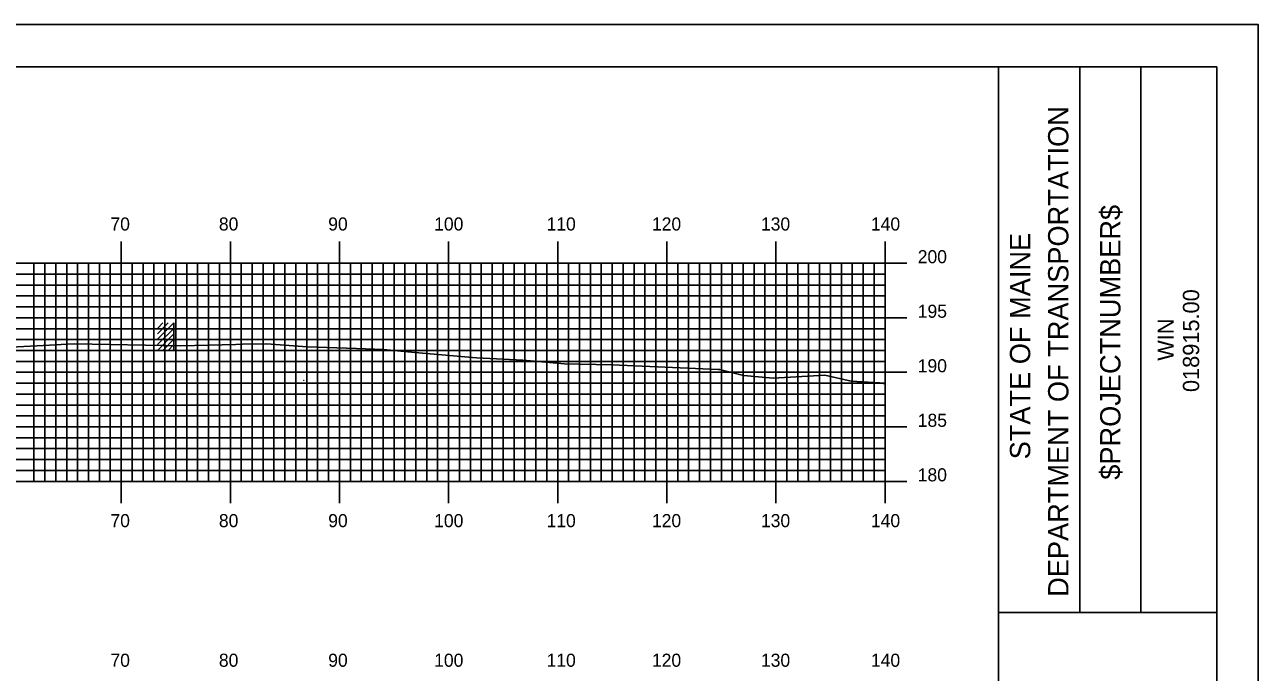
# Model space of a CAD drawing. Extents: x 1825147 to 1825490, y 442591 to 442811.
# Drawn here: x 1825373.5 to 1825486.6, y 442751.2 to 442810.5 of the extents above; entities that cross this region are included whole.
import ezdxf

# ---------------------------------------------------------------- set-up
doc = ezdxf.new("R2010")
doc.units = 0
for name, color, linetype in [('BORDER', 7, 'Continuous'), ('H_V ANNOTATION', 7, 'Continuous'), ('M_Buildings_Rooftop', 7, 'Continuous'), ('M_Utilities_Pole', 7, 'Continuous'), ('MAJOR', 7, 'Continuous'), ('MINOR', 7, 'Continuous'), ('PLOT BOUNDARY', 7, 'Continuous'), ('S_Roadway_Centerline', 7, 'Continuous')]:
    doc.layers.add(name, color=color, linetype=linetype)

msp = doc.modelspace()

# ---------------------------------------------------------------- linework, layer by layer
at = {"layer": 'BORDER'}
for p, q in [((1825462.76, 442596.67), (1825462.76, 442806.67)), ((1825470.22, 442756.66), (1825470.22, 442806.66)), ((1825475.81, 442756.66), (1825475.81, 442806.66)), ((1825462.76, 442756.65), (1825482.76, 442756.65))]:
    msp.add_line(p, q, dxfattribs=at)
msp.add_lwpolyline([(1825162.76, 442596.67), (1825482.76, 442596.67), (1825482.76, 442806.67), (1825162.76, 442806.67)], close=True, dxfattribs=at)
at = {"layer": 'M_Buildings_Rooftop'}
for p, q in [((1825385.68, 442781.7), (1825387.19, 442783.21)), ((1825385.68, 442782.19), (1825386.66, 442783.21)), ((1825385.68, 442782.68), (1825386.17, 442783.21)), ((1825385.68, 442781.21), (1825387.19, 442782.68)), ((1825387.19, 442780.68), (1825387.19, 442783.21)), ((1825385.68, 442780.68), (1825387.19, 442782.19)), ((1825386.17, 442780.68), (1825387.19, 442781.7)), ((1825386.66, 442780.68), (1825387.19, 442781.21))]:
    msp.add_line(p, q, dxfattribs=at)
at = {"layer": 'M_Utilities_Pole'}
msp.add_line((1825399.09, 442777.94), (1825399.09, 442777.93), dxfattribs=at)
msp.add_circle((1825399.09, 442777.93), 0.00417, dxfattribs=at)
at = {"layer": 'MAJOR'}
for p, q in [((1825382.36, 442790.67), (1825382.36, 442788.67)), ((1825392.36, 442790.67), (1825392.36, 442788.67)), ((1825402.36, 442790.67), (1825402.36, 442788.67)), ((1825412.36, 442790.67), (1825412.36, 442788.67)), ((1825422.36, 442790.67), (1825422.36, 442788.67)), ((1825432.36, 442790.67), (1825432.36, 442788.67)), ((1825442.36, 442790.67), (1825442.36, 442788.67)), ((1825452.36, 442790.67), (1825452.36, 442788.67)), ((1825172.36, 442788.67), (1825452.36, 442788.67)), ((1825172.36, 442788.67), (1825452.36, 442788.67)), ((1825382.36, 442768.67), (1825382.36, 442788.67)), ((1825392.36, 442768.67), (1825392.36, 442788.67)), ((1825402.36, 442768.67), (1825402.36, 442788.67)), ((1825412.36, 442768.67), (1825412.36, 442788.67)), ((1825422.36, 442768.67), (1825422.36, 442788.67)), ((1825432.36, 442768.67), (1825432.36, 442788.67)), ((1825442.36, 442768.67), (1825442.36, 442788.67)), ((1825454.37, 442788.67), (1825450.36, 442788.67)), ((1825452.36, 442768.67), (1825452.36, 442788.67)), ((1825452.36, 442768.67), (1825452.36, 442788.67)), ((1825172.36, 442783.67), (1825452.36, 442783.67)), ((1825454.37, 442783.67), (1825450.36, 442783.67)), ((1825172.36, 442778.67), (1825452.36, 442778.67)), ((1825454.37, 442778.67), (1825450.36, 442778.67)), ((1825172.36, 442773.67), (1825452.36, 442773.67)), ((1825454.37, 442773.67), (1825450.36, 442773.67)), ((1825172.36, 442768.67), (1825452.36, 442768.67)), ((1825172.36, 442768.67), (1825452.36, 442768.67)), ((1825382.36, 442766.66), (1825382.36, 442768.67)), ((1825392.36, 442766.66), (1825392.36, 442768.67)), ((1825402.36, 442766.66), (1825402.36, 442768.67)), ((1825412.36, 442766.66), (1825412.36, 442768.67)), ((1825422.36, 442766.66), (1825422.36, 442768.67)), ((1825432.36, 442766.66), (1825432.36, 442768.67)), ((1825442.36, 442766.66), (1825442.36, 442768.67)), ((1825454.37, 442768.67), (1825450.36, 442768.67)), ((1825452.36, 442766.66), (1825452.36, 442768.67))]:
    msp.add_line(p, q, dxfattribs=at)
at = {"layer": 'MINOR'}
for p, q in [((1825374.36, 442768.67), (1825374.36, 442788.67)), ((1825375.36, 442768.67), (1825375.36, 442788.67)), ((1825376.36, 442768.67), (1825376.36, 442788.67)), ((1825377.36, 442768.67), (1825377.36, 442788.67)), ((1825378.36, 442768.67), (1825378.36, 442788.67)), ((1825379.36, 442768.67), (1825379.36, 442788.67)), ((1825380.36, 442768.67), (1825380.36, 442788.67)), ((1825381.36, 442768.67), (1825381.36, 442788.67)), ((1825383.36, 442768.67), (1825383.36, 442788.67)), ((1825384.36, 442768.67), (1825384.36, 442788.67)), ((1825385.36, 442768.67), (1825385.36, 442788.67)), ((1825386.36, 442768.67), (1825386.36, 442788.67)), ((1825387.36, 442768.67), (1825387.36, 442788.67)), ((1825388.36, 442768.67), (1825388.36, 442788.67)), ((1825389.36, 442768.67), (1825389.36, 442788.67)), ((1825390.36, 442768.67), (1825390.36, 442788.67)), ((1825391.36, 442768.67), (1825391.36, 442788.67)), ((1825393.36, 442768.67), (1825393.36, 442788.67)), ((1825394.36, 442768.67), (1825394.36, 442788.67)), ((1825395.36, 442768.67), (1825395.36, 442788.67)), ((1825396.36, 442768.67), (1825396.36, 442788.67)), ((1825397.36, 442768.67), (1825397.36, 442788.67)), ((1825398.36, 442768.67), (1825398.36, 442788.67)), ((1825399.36, 442768.67), (1825399.36, 442788.67)), ((1825400.36, 442768.67), (1825400.36, 442788.67)), ((1825401.36, 442768.67), (1825401.36, 442788.67)), ((1825403.36, 442768.67), (1825403.36, 442788.67)), ((1825404.36, 442768.67), (1825404.36, 442788.67)), ((1825405.36, 442768.67), (1825405.36, 442788.67)), ((1825406.36, 442768.67), (1825406.36, 442788.67)), ((1825407.36, 442768.67), (1825407.36, 442788.67)), ((1825408.36, 442768.67), (1825408.36, 442788.67)), ((1825409.36, 442768.67), (1825409.36, 442788.67)), ((1825410.36, 442768.67), (1825410.36, 442788.67)), ((1825411.36, 442768.67), (1825411.36, 442788.67)), ((1825413.36, 442768.67), (1825413.36, 442788.67)), ((1825414.36, 442768.67), (1825414.36, 442788.67)), ((1825415.36, 442768.67), (1825415.36, 442788.67)), ((1825416.36, 442768.67), (1825416.36, 442788.67)), ((1825417.36, 442768.67), (1825417.36, 442788.67)), ((1825418.36, 442768.67), (1825418.36, 442788.67)), ((1825419.36, 442768.67), (1825419.36, 442788.67)), ((1825420.36, 442768.67), (1825420.36, 442788.67)), ((1825421.36, 442768.67), (1825421.36, 442788.67)), ((1825423.36, 442768.67), (1825423.36, 442788.67)), ((1825424.36, 442768.67), (1825424.36, 442788.67)), ((1825425.36, 442768.67), (1825425.36, 442788.67)), ((1825426.36, 442768.67), (1825426.36, 442788.67)), ((1825427.36, 442768.67), (1825427.36, 442788.67)), ((1825428.36, 442768.67), (1825428.36, 442788.67)), ((1825429.36, 442768.67), (1825429.36, 442788.67)), ((1825430.36, 442768.67), (1825430.36, 442788.67)), ((1825431.36, 442768.67), (1825431.36, 442788.67)), ((1825433.36, 442768.67), (1825433.36, 442788.67)), ((1825434.36, 442768.67), (1825434.36, 442788.67)), ((1825435.36, 442768.67), (1825435.36, 442788.67)), ((1825436.36, 442768.67), (1825436.36, 442788.67)), ((1825437.36, 442768.67), (1825437.36, 442788.67)), ((1825438.36, 442768.67), (1825438.36, 442788.67)), ((1825439.36, 442768.67), (1825439.36, 442788.67)), ((1825440.36, 442768.67), (1825440.36, 442788.67)), ((1825441.36, 442768.67), (1825441.36, 442788.67)), ((1825443.36, 442768.67), (1825443.36, 442788.67)), ((1825444.36, 442768.67), (1825444.36, 442788.67)), ((1825445.36, 442768.67), (1825445.36, 442788.67)), ((1825446.36, 442768.67), (1825446.36, 442788.67)), ((1825447.36, 442768.67), (1825447.36, 442788.67)), ((1825448.36, 442768.67), (1825448.36, 442788.67)), ((1825449.36, 442768.67), (1825449.36, 442788.67)), ((1825450.36, 442768.67), (1825450.36, 442788.67)), ((1825451.36, 442768.67), (1825451.36, 442788.67)), ((1825172.36, 442787.67), (1825452.36, 442787.67)), ((1825452.36, 442787.67), (1825450.36, 442787.67)), ((1825172.36, 442786.67), (1825452.36, 442786.67)), ((1825452.36, 442786.67), (1825450.36, 442786.67)), ((1825172.36, 442785.67), (1825452.36, 442785.67)), ((1825452.36, 442785.67), (1825450.36, 442785.67)), ((1825172.36, 442784.67), (1825452.36, 442784.67)), ((1825452.36, 442784.67), (1825450.36, 442784.67)), ((1825172.36, 442782.67), (1825452.36, 442782.67)), ((1825452.36, 442782.67), (1825450.36, 442782.67)), ((1825172.36, 442781.67), (1825452.36, 442781.67)), ((1825452.36, 442781.67), (1825450.36, 442781.67)), ((1825172.36, 442780.67), (1825452.36, 442780.67)), ((1825452.36, 442780.67), (1825450.36, 442780.67)), ((1825172.36, 442779.67), (1825452.36, 442779.67)), ((1825452.36, 442779.67), (1825450.36, 442779.67)), ((1825172.36, 442777.67), (1825452.36, 442777.67)), ((1825452.36, 442777.67), (1825450.36, 442777.67)), ((1825172.36, 442776.67), (1825452.36, 442776.67)), ((1825452.36, 442776.67), (1825450.36, 442776.67)), ((1825172.36, 442775.67), (1825452.36, 442775.67)), ((1825452.36, 442775.67), (1825450.36, 442775.67)), ((1825172.36, 442774.67), (1825452.36, 442774.67)), ((1825452.36, 442774.67), (1825450.36, 442774.67)), ((1825172.36, 442772.67), (1825452.36, 442772.67)), ((1825452.36, 442772.67), (1825450.36, 442772.67)), ((1825172.36, 442771.67), (1825452.36, 442771.67)), ((1825452.36, 442771.67), (1825450.36, 442771.67)), ((1825172.36, 442770.67), (1825452.36, 442770.67)), ((1825452.36, 442770.67), (1825450.36, 442770.67)), ((1825172.36, 442769.67), (1825452.36, 442769.67)), ((1825452.36, 442769.67), (1825450.36, 442769.67))]:
    msp.add_line(p, q, dxfattribs=at)
at = {"layer": 'PLOT BOUNDARY'}
msp.add_lwpolyline([(1825146.57, 442590.55), (1825486.57, 442590.55), (1825486.57, 442810.55), (1825146.57, 442810.55)], close=True, dxfattribs=at)
at = {"layer": 'S_Roadway_Centerline'}
msp.add_lwpolyline([(1825365.76, 442780.65), (1825375.79, 442781.17), (1825377.39, 442781.25), (1825378.07, 442781.29), (1825387.82, 442781.11), (1825392.86, 442781.21), (1825393.46, 442781.26), (1825395.67, 442781.28), (1825399.41, 442781.02), (1825403.93, 442780.84), (1825406.4, 442780.76), (1825409.27, 442780.5), (1825414.92, 442779.99), (1825419.16, 442779.77), (1825422.97, 442779.45), (1825427.33, 442779.34), (1825437.06, 442778.93), (1825437.2, 442778.93), (1825439.4, 442778.37), (1825439.75, 442778.36), (1825442.1, 442778.12), (1825446.83, 442778.4), (1825449.26, 442777.87), (1825451.85, 442777.7), (1825452.36, 442777.62)], dxfattribs=at)

# ---------------------------------------------------------------- texts
at = {"layer": 'BORDER'}
for s, height, p in [('DEPARTMENT OF TRANSPORTATION', 1.8635, (1825469.17, 442758.08)), ('$PROJECTNUMBER$', 1.8635, (1825473.94, 442768.82)), ('STATE OF MAINE', 1.8635, (1825465.67, 442770.69)), ('018915.00', 1.491, (1825481.15, 442776.86)), ('WIN', 1.491, (1825478.83, 442779.73))]:
    msp.add_text(s, height=height, rotation=90, dxfattribs=at).set_placement(p)
at = {"layer": 'H_V ANNOTATION'}
for s, p in [('70', (1825381.37, 442791.67)), ('80', (1825391.31, 442791.67)), ('90', (1825401.33, 442791.67)), ('100', (1825411.04, 442791.67)), ('110', (1825421.34, 442791.67)), ('120', (1825431, 442791.67)), ('130', (1825440.99, 442791.67)), ('140', (1825451.07, 442791.67)), ('200', (1825455.36, 442788.67)), ('195', (1825455.36, 442783.67)), ('190', (1825455.36, 442778.67)), ('185', (1825455.36, 442773.67)), ('180', (1825455.36, 442768.67)), ('70', (1825381.37, 442764.47)), ('80', (1825391.31, 442764.47)), ('90', (1825401.33, 442764.47)), ('100', (1825411.04, 442764.47)), ('110', (1825421.34, 442764.47)), ('120', (1825431, 442764.47)), ('130', (1825440.99, 442764.47)), ('140', (1825451.07, 442764.47)), ('70', (1825381.37, 442751.67)), ('80', (1825391.31, 442751.67)), ('90', (1825401.33, 442751.67)), ('100', (1825411.04, 442751.67)), ('110', (1825421.34, 442751.67)), ('120', (1825431, 442751.67)), ('130', (1825440.99, 442751.67)), ('140', (1825451.07, 442751.67))]:
    msp.add_text(s, height=1.2, dxfattribs=at).set_placement(p)

doc.saveas('drawing.dxf')
